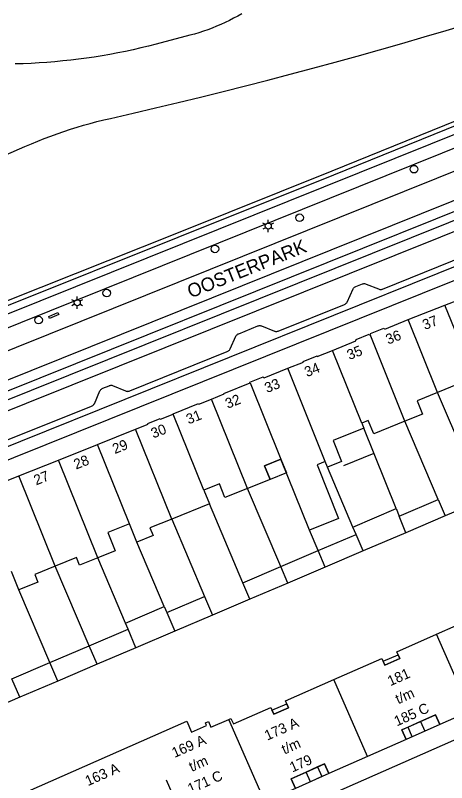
# Model space of a CAD drawing. Extents: x 122462 to 123306, y 485548 to 486417.
# Drawn here: x 123106.7 to 123170.2, y 485663.3 to 485776.1 of the extents above; entities that cross this region are included whole.
import ezdxf

# ---------------------------------------------------------------- set-up
doc = ezdxf.new("R2010")
doc.units = 0
for name, color, linetype in [('B-WE-IE-MEUBILAIR_WEGMEUBILAIR_VERKEERSBORD-S', 7, 'Continuous'), ('Level 1', 7, 'Continuous'), ('Level 10', 7, 'Continuous'), ('Level 11', 7, 'Continuous'), ('Level 17', 7, 'Continuous'), ('Level 19', 7, 'Continuous'), ('Level 2', 7, 'Continuous'), ('Level 30', 7, 'Continuous'), ('Level 37', 7, 'Continuous'), ('Level 4', 7, 'Continuous'), ('Level 40', 7, 'Continuous'), ('Level 50', 7, 'Continuous'), ('Level 53', 7, 'Continuous'), ('N werkgrens', 7, 'Continuous'), ('N-WE-AL-T25', 7, 'Continuous'), ('N-WE-GR-BOOM_DOORWORTELBARE RUIMTE-G', 7, 'Continuous')]:
    doc.layers.add(name, color=color, linetype=linetype)

msp = doc.modelspace()

# ---------------------------------------------------------------- linework, layer by layer
at = {"layer": 'Level 1'}
for p, q in [((123169.91, 485733.47), (123175.31, 485735.57)), ((123164.49, 485731.34), (123169.91, 485733.47)), ((123157.65, 485716.14), (123157.95, 485715.4)), ((123118.79, 485712.97), (123124.36, 485715.23)), ((123113.02, 485710.69), (123118.79, 485712.97)), ((123107.21, 485708.37), (123113.02, 485710.69)), ((123149.97, 485700.4), (123145.76, 485710.84)), ((123152.62, 485709.66), (123152.29, 485710.48)), ((123101.4, 485706.05), (123107.21, 485708.37)), ((123134.43, 485706.27), (123135.24, 485704.25)), ((123135.24, 485704.25), (123129.69, 485702.01)), ((123124.56, 485698.65), (123123.49, 485701.32)), ((123107.2, 485691.65), (123106.13, 485694.32)), ((123166.3, 485672.27), (123164.47, 485671.46)), ((123151.16, 485665.59), (123149.48, 485664.84))]:
    msp.add_line(p, q, dxfattribs=at)
for points in [[(123158.89, 485729.17), (123158.98, 485729.21), (123158.94, 485729.3), (123160.9, 485730.1), (123160.94, 485730), (123161.03, 485730.04), (123161.07, 485729.95), (123164.49, 485731.34)], [(123153.34, 485726.82), (123156.81, 485728.21), (123156.77, 485728.31), (123156.86, 485728.34), (123156.82, 485728.44), (123158.75, 485729.22), (123158.79, 485729.13), (123158.89, 485729.17)], [(123146.76, 485724.19), (123149.07, 485725.1), (123149.03, 485725.19), (123151.08, 485726.01), (123151.12, 485725.92), (123153.34, 485726.82)], [(123141.24, 485722.06), (123141.21, 485722.15), (123143.14, 485722.96), (123143.17, 485722.86), (123143.26, 485722.9), (123143.29, 485722.8), (123146.76, 485724.19)], [(123135.55, 485719.67), (123137.42, 485720.43), (123137.39, 485720.51), (123141.24, 485722.06)], [(123175, 485720.85), (123172.61, 485719.89), (123171.82, 485721.85), (123168.81, 485720.64)], [(123168.81, 485720.64), (123165.82, 485719.43), (123166.61, 485717.47), (123164.02, 485716.43)], [(123129.93, 485717.43), (123129.9, 485717.51), (123133.65, 485719), (123133.68, 485718.92), (123135.55, 485719.67)], [(123124.36, 485715.23), (123126.24, 485715.99), (123126.2, 485716.09), (123127.99, 485716.81), (123128.03, 485716.69), (123129.93, 485717.43)], [(123164.02, 485716.43), (123159.42, 485714.57), (123158.63, 485716.53), (123157.65, 485716.14)], [(123157.95, 485715.4), (123153.46, 485713.59), (123154.7, 485710.5), (123152.62, 485709.66)], [(123145.76, 485710.84), (123143.36, 485709.87), (123144.18, 485707.85), (123140.86, 485706.51)], [(123152.29, 485710.48), (123151.09, 485710), (123154.26, 485702.12), (123149.97, 485700.4)], [(123140.86, 485706.51), (123137.53, 485705.18), (123136.72, 485707.19), (123134.43, 485706.27)], [(123123.49, 485701.32), (123120.3, 485700.04), (123121.38, 485697.36), (123118.81, 485696.33)], [(123129.69, 485702.01), (123126.5, 485700.73), (123126.95, 485699.61), (123124.56, 485698.65)], [(123118.81, 485696.33), (123116.14, 485695.25), (123115.68, 485696.37), (123112.55, 485695.11)], [(123112.55, 485695.11), (123109.54, 485693.9), (123110, 485692.78), (123107.2, 485691.65)], [(123168.65, 485685.1), (123174.44, 485687.65), (123174.88, 485686.64), (123177.07, 485687.61), (123176.63, 485688.62), (123182.35, 485691.13)], [(123153.53, 485678.43), (123160.61, 485681.56), (123161.05, 485680.55), (123163.26, 485681.52), (123162.81, 485682.53), (123168.65, 485685.1)], [(123138.09, 485672.59), (123138.41, 485672.74), (123138.77, 485671.92), (123144.26, 485674.35), (123144.7, 485673.34), (123146.89, 485674.3), (123146.45, 485675.31), (123153.53, 485678.43)], [(123173.62, 485673.8), (123169.15, 485671.83), (123168.52, 485673.24), (123166.3, 485672.27)], [(123102.51, 485656.92), (123105.15, 485658.08), (123104.79, 485658.91), (123105.25, 485659.11), (123105.41, 485658.74), (123107.6, 485659.71), (123106.9, 485661.32), (123131.91, 485672.33), (123132.61, 485670.73), (123134.81, 485671.7), (123134.65, 485672.06), (123135.1, 485672.26), (123135.47, 485671.44), (123138.09, 485672.59)], [(123164.47, 485671.46), (123163.56, 485671.06), (123164.18, 485669.64), (123158.51, 485667.14)], [(123158.51, 485667.14), (123152.81, 485664.62), (123152.19, 485666.04), (123151.16, 485665.59)], [(123149.48, 485664.84), (123147.26, 485663.87), (123147.89, 485662.45), (123143.44, 485660.48)]]:
    msp.add_lwpolyline(points, dxfattribs=at)
at = {"layer": 'Level 10'}
for points in [[(123144.18, 485707.85), (123143.36, 485709.87), (123145.76, 485710.84), (123146.58, 485708.82), (123144.18, 485707.85)], [(123161.05, 485680.55), (123160.8, 485681.13), (123163, 485682.1), (123163.26, 485681.52), (123161.05, 485680.55)], [(123144.7, 485673.34), (123144.45, 485673.92), (123146.64, 485674.88), (123146.89, 485674.3), (123144.7, 485673.34)], [(123164.18, 485669.64), (123163.56, 485671.06), (123168.52, 485673.24), (123169.15, 485671.83), (123164.18, 485669.64)], [(123147.89, 485662.45), (123147.26, 485663.87), (123149.48, 485664.84), (123152.19, 485666.04), (123152.81, 485664.62), (123147.89, 485662.45)]]:
    msp.add_lwpolyline(points, dxfattribs=at)
at = {"layer": 'Level 11'}
msp.add_line((123159.45, 485711.66), (123154.96, 485709.85), dxfattribs=at)
at = {"layer": 'Level 17'}
for points in [[(123306.02, 485793.23), (123281.54, 485783.41), (123199.54, 485750.48), (123092.05, 485707.28), (123051.43, 485690.97), (123010.46, 485674.56), (123010.38, 485674.54), (123010.31, 485674.53), (123010.23, 485674.54)], [(123010.9, 485672.76), (123016.12, 485674.9), (123023.42, 485677.77), (123052.25, 485689.33), (123092.64, 485705.53), (123175.87, 485738.97), (123200.14, 485748.71), (123282.24, 485781.66), (123306.02, 485791.2)], [(123033.3, 485704.16), (123033.55, 485703.56), (123043.09, 485707.71), (123057.87, 485714.13), (123066.6, 485717.66), (123085.63, 485725.38), (123105.66, 485733.48), (123130.67, 485743.46), (123153.55, 485752.61), (123177.38, 485762.27), (123193.41, 485768.64), (123221.97, 485779.99), (123224.29, 485780.91)], [(123193.77, 485767.58), (123058.27, 485713.2), (123043.56, 485706.78)], [(123194.37, 485765.79), (123057.92, 485710.97), (123044.4, 485705.07)], [(123045.06, 485703.75), (123076.2, 485713.96), (123076.3, 485713.99), (123076.38, 485714.04), (123076.46, 485714.1), (123076.53, 485714.17), (123076.59, 485714.25), (123076.63, 485714.34), (123077.4, 485716.16), (123077.45, 485716.26), (123077.51, 485716.34), (123077.58, 485716.42), (123077.66, 485716.48), (123077.74, 485716.54), (123077.84, 485716.58), (123092.54, 485721.56), (123187.75, 485759.76)], [(123155.21, 485733.62), (123155.29, 485733.67), (123155.37, 485733.74), (123155.45, 485733.81), (123155.51, 485733.89), (123156.4, 485735.86), (123156.46, 485735.95), (123156.52, 485736.03), (123156.6, 485736.1), (123156.69, 485736.16), (123156.78, 485736.2), (123157.78, 485736.6), (123157.88, 485736.62), (123157.98, 485736.64), (123158.09, 485736.64), (123158.19, 485736.62), (123158.29, 485736.58), (123160.14, 485735.85), (123160.22, 485735.81), (123160.3, 485735.78), (123160.39, 485735.77), (123160.48, 485735.77), (123160.57, 485735.78), (123160.65, 485735.8), (123160.73, 485735.84), (123175.16, 485741.63)], [(123089.55, 485707.3), (123117.89, 485718.63), (123117.99, 485718.68), (123118.09, 485718.74), (123118.18, 485718.81), (123118.26, 485718.9), (123118.33, 485718.99), (123119.13, 485720.86), (123119.2, 485720.96), (123119.27, 485721.05), (123119.36, 485721.14), (123119.45, 485721.21), (123119.56, 485721.26), (123120.48, 485721.62), (123120.56, 485721.66), (123120.65, 485721.68), (123120.73, 485721.7), (123120.82, 485721.7), (123120.9, 485721.69), (123120.99, 485721.67), (123122.91, 485720.87), (123122.99, 485720.84), (123123.08, 485720.81), (123123.17, 485720.8), (123123.26, 485720.81), (123123.35, 485720.82), (123123.43, 485720.85), (123123.51, 485720.9), (123137.88, 485726.66), (123137.97, 485726.7), (123138.05, 485726.75), (123138.12, 485726.81), (123138.19, 485726.88), (123138.24, 485726.96), (123138.29, 485727.05), (123139.14, 485728.91), (123139.19, 485728.99), (123139.25, 485729.07), (123139.32, 485729.13), (123139.39, 485729.19), (123139.48, 485729.24), (123139.56, 485729.28), (123142.35, 485730.41), (123142.47, 485730.44), (123142.59, 485730.46), (123142.7, 485730.46), (123142.82, 485730.45), (123142.93, 485730.42), (123144.8, 485729.67), (123144.89, 485729.64), (123144.99, 485729.62), (123145.09, 485729.62), (123145.19, 485729.62), (123145.28, 485729.64), (123145.38, 485729.67), (123155.12, 485733.57), (123155.21, 485733.62)], [(123140.62, 485656.07), (123204.71, 485684.26)]]:
    msp.add_lwpolyline(points, dxfattribs=at)
at = {"layer": 'Level 19'}
for p, q in [((123175.52, 485704.88), (123168.81, 485720.64)), ((123168.92, 485704.93), (123164.02, 485716.43)), ((123162.72, 485703.56), (123157.95, 485715.4)), ((123156.37, 485700.85), (123152.62, 485709.66)), ((123145.74, 485695.06), (123140.86, 485706.51)), ((123175.52, 485704.88), (123169.95, 485702.51)), ((123140.17, 485692.68), (123135.24, 485704.25)), ((123129.69, 485702.01), (123134.53, 485690.66)), ((123151.25, 485697.4), (123149.97, 485700.4)), ((123128.6, 485689.18), (123124.56, 485698.65)), ((123122.89, 485686.75), (123118.81, 485696.33)), ((123117.54, 485683.42), (123112.55, 485695.11)), ((123111.76, 485680.96), (123107.2, 485691.65)), ((123141.21, 485690.26), (123135.7, 485687.92))]:
    msp.add_line(p, q, dxfattribs=at)
for points in [[(123140.01, 485776.31), (123139.41, 485775.96), (123138.8, 485775.63), (123138.19, 485775.32), (123137.57, 485775.02), (123136.94, 485774.73), (123136.3, 485774.46), (123135.66, 485774.2), (123135.02, 485773.95), (123134.36, 485773.73), (123133.71, 485773.51), (123133.04, 485773.31), (123132.38, 485773.13), (123127.43, 485771.84), (123126.3, 485771.55), (123125.17, 485771.27), (123124.03, 485771.02), (123122.89, 485770.77), (123121.75, 485770.54), (123120.6, 485770.33), (123119.45, 485770.13), (123118.3, 485769.94), (123117.14, 485769.77), (123115.98, 485769.62), (123114.83, 485769.48), (123113.67, 485769.36), (123112.5, 485769.24), (123111.34, 485769.15), (123110.18, 485769.07), (123109.01, 485769.01), (123107.85, 485768.96), (123106.68, 485768.92)], [(123071.69, 485740.89), (123108.1, 485756.8), (123109.04, 485757.2), (123109.98, 485757.59), (123110.93, 485757.96), (123111.89, 485758.32), (123112.85, 485758.67), (123113.81, 485759), (123114.78, 485759.32), (123115.76, 485759.62), (123116.73, 485759.91), (123117.72, 485760.19), (123118.7, 485760.45), (123119.69, 485760.7), (123120.69, 485760.93), (123124.01, 485761.69), (123127.33, 485762.46), (123130.64, 485763.25), (123133.95, 485764.05), (123137.26, 485764.87), (123140.56, 485765.7), (123143.86, 485766.55), (123147.15, 485767.41), (123150.44, 485768.29), (123153.73, 485769.18), (123157.01, 485770.08), (123160.29, 485771), (123163.57, 485771.94), (123166.84, 485772.89), (123170.1, 485773.85), (123173.37, 485774.83)]]:
    msp.add_lwpolyline(points, dxfattribs=at)
at = {"layer": 'Level 2'}
for p, q in [((123163.15, 485702.48), (123168.92, 485704.93)), ((123168.92, 485704.93), (123169.95, 485702.51)), ((123156.37, 485700.85), (123162.72, 485703.56)), ((123162.72, 485703.56), (123163.15, 485702.48)), ((123164.14, 485700.03), (123163.15, 485702.48)), ((123169.95, 485702.51), (123164.14, 485700.03)), ((123151.25, 485697.4), (123156.83, 485699.78)), ((123156.83, 485699.78), (123156.37, 485700.85)), ((123157.86, 485697.36), (123156.83, 485699.78)), ((123164.14, 485700.03), (123157.86, 485697.36)), ((123145.74, 485695.06), (123151.25, 485697.4)), ((123152.28, 485694.98), (123151.25, 485697.4)), ((123157.86, 485697.36), (123152.28, 485694.98)), ((123140.17, 485692.68), (123145.74, 485695.06)), ((123146.77, 485692.63), (123145.74, 485695.06)), ((123152.28, 485694.98), (123146.77, 485692.63)), ((123141.21, 485690.26), (123140.17, 485692.68)), ((123146.77, 485692.63), (123141.21, 485690.26)), ((123128.98, 485688.29), (123134.53, 485690.66)), ((123134.53, 485690.66), (123135.7, 485687.92)), ((123122.89, 485686.75), (123128.6, 485689.18)), ((123128.6, 485689.18), (123128.98, 485688.29)), ((123128.98, 485688.29), (123130.14, 485685.55)), ((123135.7, 485687.92), (123130.14, 485685.55)), ((123123.27, 485685.86), (123122.89, 485686.75)), ((123117.54, 485683.42), (123123.27, 485685.86)), ((123124.44, 485683.12), (123123.27, 485685.86)), ((123130.14, 485685.55), (123124.44, 485683.12)), ((123111.76, 485680.96), (123117.54, 485683.42)), ((123118.71, 485680.68), (123117.54, 485683.42)), ((123124.44, 485683.12), (123118.71, 485680.68)), ((123106.16, 485678.57), (123111.76, 485680.96)), ((123112.93, 485678.21), (123111.76, 485680.96)), ((123118.71, 485680.68), (123112.93, 485678.21)), ((123107.33, 485675.83), (123106.16, 485678.57)), ((123112.93, 485678.21), (123107.33, 485675.83)), ((123107.33, 485675.83), (123101.74, 485673.45))]:
    msp.add_line(p, q, dxfattribs=at)
at = {"layer": 'Level 30'}
for points in [[(123166.3, 485672.27), (123166.93, 485670.85), (123165.09, 485670.04), (123164.47, 485671.46)], [(123151.16, 485665.59), (123151.79, 485664.17), (123150.1, 485663.42), (123149.48, 485664.84)]]:
    msp.add_lwpolyline(points, dxfattribs=at)
at = {"layer": 'Level 37'}
for points in [[(123051.53, 485700.77), (123241.71, 485777.16)], [(123052.08, 485699.4), (123242.53, 485775.87)], [(123019.64, 485685.1), (123243.14, 485774.75)], [(123020.18, 485683.72), (123243.94, 485773.45)]]:
    msp.add_lwpolyline(points, dxfattribs=at)
at = {"layer": 'Level 4'}
for p, q in [((123175, 485720.85), (123169.91, 485733.47)), ((123168.81, 485720.64), (123164.49, 485731.34)), ((123164.02, 485716.43), (123158.89, 485729.17)), ((123157.65, 485716.14), (123153.34, 485726.82)), ((123152.29, 485710.48), (123146.76, 485724.19)), ((123141.24, 485722.06), (123145.76, 485710.84)), ((123140.86, 485706.51), (123135.55, 485719.67)), ((123134.43, 485706.27), (123129.93, 485717.43)), ((123129.69, 485702.01), (123124.36, 485715.23)), ((123123.49, 485701.32), (123118.79, 485712.97)), ((123118.81, 485696.33), (123113.02, 485710.69)), ((123112.55, 485695.11), (123107.21, 485708.37)), ((123173.62, 485673.8), (123168.65, 485685.1)), ((123158.51, 485667.14), (123153.53, 485678.43)), ((123143.44, 485660.48), (123138.09, 485672.59))]:
    msp.add_line(p, q, dxfattribs=at)
at = {"layer": 'Level 40'}
msp.add_lwpolyline([(123111.72, 485731.5), (123111.59, 485731.8), (123112.95, 485732.38), (123113.08, 485732.08), (123111.72, 485731.5)], dxfattribs=at)
at = {"layer": 'Level 50'}
for p, q in [((123143.51, 485745.31), (123143.12, 485745.54)), ((123143.9, 485745.54), (123143.9, 485745.99)), ((123144.68, 485745.54), (123144.29, 485745.31)), ((123143.51, 485744.86), (123143.12, 485744.64)), ((123143.9, 485744.19), (123143.9, 485744.64)), ((123144.68, 485744.64), (123144.29, 485744.86)), ((123115.4, 485734.05), (123115.01, 485734.27)), ((123115.79, 485734.27), (123115.79, 485734.72)), ((123116.57, 485734.27), (123116.18, 485734.05)), ((123115.4, 485733.6), (123115.01, 485733.37)), ((123115.79, 485732.92), (123115.79, 485733.37)), ((123116.57, 485733.37), (123116.18, 485733.6))]:
    msp.add_line(p, q, dxfattribs=at)
for centre in [(123143.9, 485745.09), (123115.79, 485733.82)]:
    msp.add_circle(centre, 0.45, dxfattribs=at)
at = {"layer": 'Level 53'}
for centre in [(123165.35, 485753.46), (123148.52, 485746.32), (123136.06, 485741.74), (123120.14, 485735.25), (123110.11, 485731.28)]:
    msp.add_circle(centre, 0.56, dxfattribs=at)
at = {"layer": 'N werkgrens'}
msp.add_lwpolyline([(123033.3, 485704.16), (123057.62, 485714.73), (123066.35, 485718.26), (123085.38, 485725.98), (123105.42, 485734.09), (123130.43, 485744.07), (123153.31, 485753.22), (123177.14, 485762.88), (123221.73, 485780.6), (123233.12, 485785.09)], dxfattribs=at)
at = {"layer": 'N-WE-AL-T25'}
msp.add_line((123131.15, 485658.57), (123128.91, 485663.66), dxfattribs=at)

# ---------------------------------------------------------------- texts
at = {"layer": 'B-WE-IE-MEUBILAIR_WEGMEUBILAIR_VERKEERSBORD-S'}
for s, rotation, p in [('37', 21.7684, (123166.95, 485729.81)), ('36', 21.7684, (123161.55, 485727.66)), ('35', 21.7684, (123155.84, 485725.39)), ('34', 21.7684, (123149.59, 485722.88)), ('33', 21.7684, (123143.72, 485720.54)), ('32', 21.7684, (123137.93, 485718.23)), ('31', 21.7684, (123132.18, 485715.93)), ('30', 21.7684, (123126.99, 485713.86)), ('29', 22.1024, (123121.33, 485711.57)), ('28', 21.567, (123115.62, 485709.3)), ('27', 21.7386, (123109.75, 485706.97)), ('181', 23.8069, (123161.86, 485677.45)), ('t/m', 23.8069, (123163.02, 485674.8)), ('185 C', 23.8069, (123162.83, 485671.55)), ('173 A', 23.8069, (123143.75, 485669.45)), ('169 A', 23.7702, (123130.11, 485666.91)), ('t/m', 23.8069, (123146.28, 485667.41)), ('179', 23.8069, (123147.45, 485664.77)), ('163 A', 23.7837, (123117.36, 485662.76)), ('t/m', 23.7702, (123132.64, 485664.86)), ('171 C', 23.7702, (123132.44, 485661.62))]:
    msp.add_text(s, height=1.5, rotation=rotation, dxfattribs=at).set_placement(p)
at = {"layer": 'N-WE-GR-BOOM_DOORWORTELBARE RUIMTE-G'}
msp.add_text('OOSTERPARK', height=2, rotation=21.778, dxfattribs=at).set_placement((123132.48, 485734.46))

doc.saveas('drawing.dxf')
